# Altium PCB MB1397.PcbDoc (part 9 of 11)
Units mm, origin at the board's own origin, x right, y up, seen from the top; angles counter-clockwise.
Board outline 118.24 x 172.86 mm, 6 copper layers (Top Layer, L2_GND, L3_VCC, L4_SIG, L5_GND, Bottom Layer), stack 1.631 mm thick; 819 components, 632 nets, 2875 pads, 1523 vias.
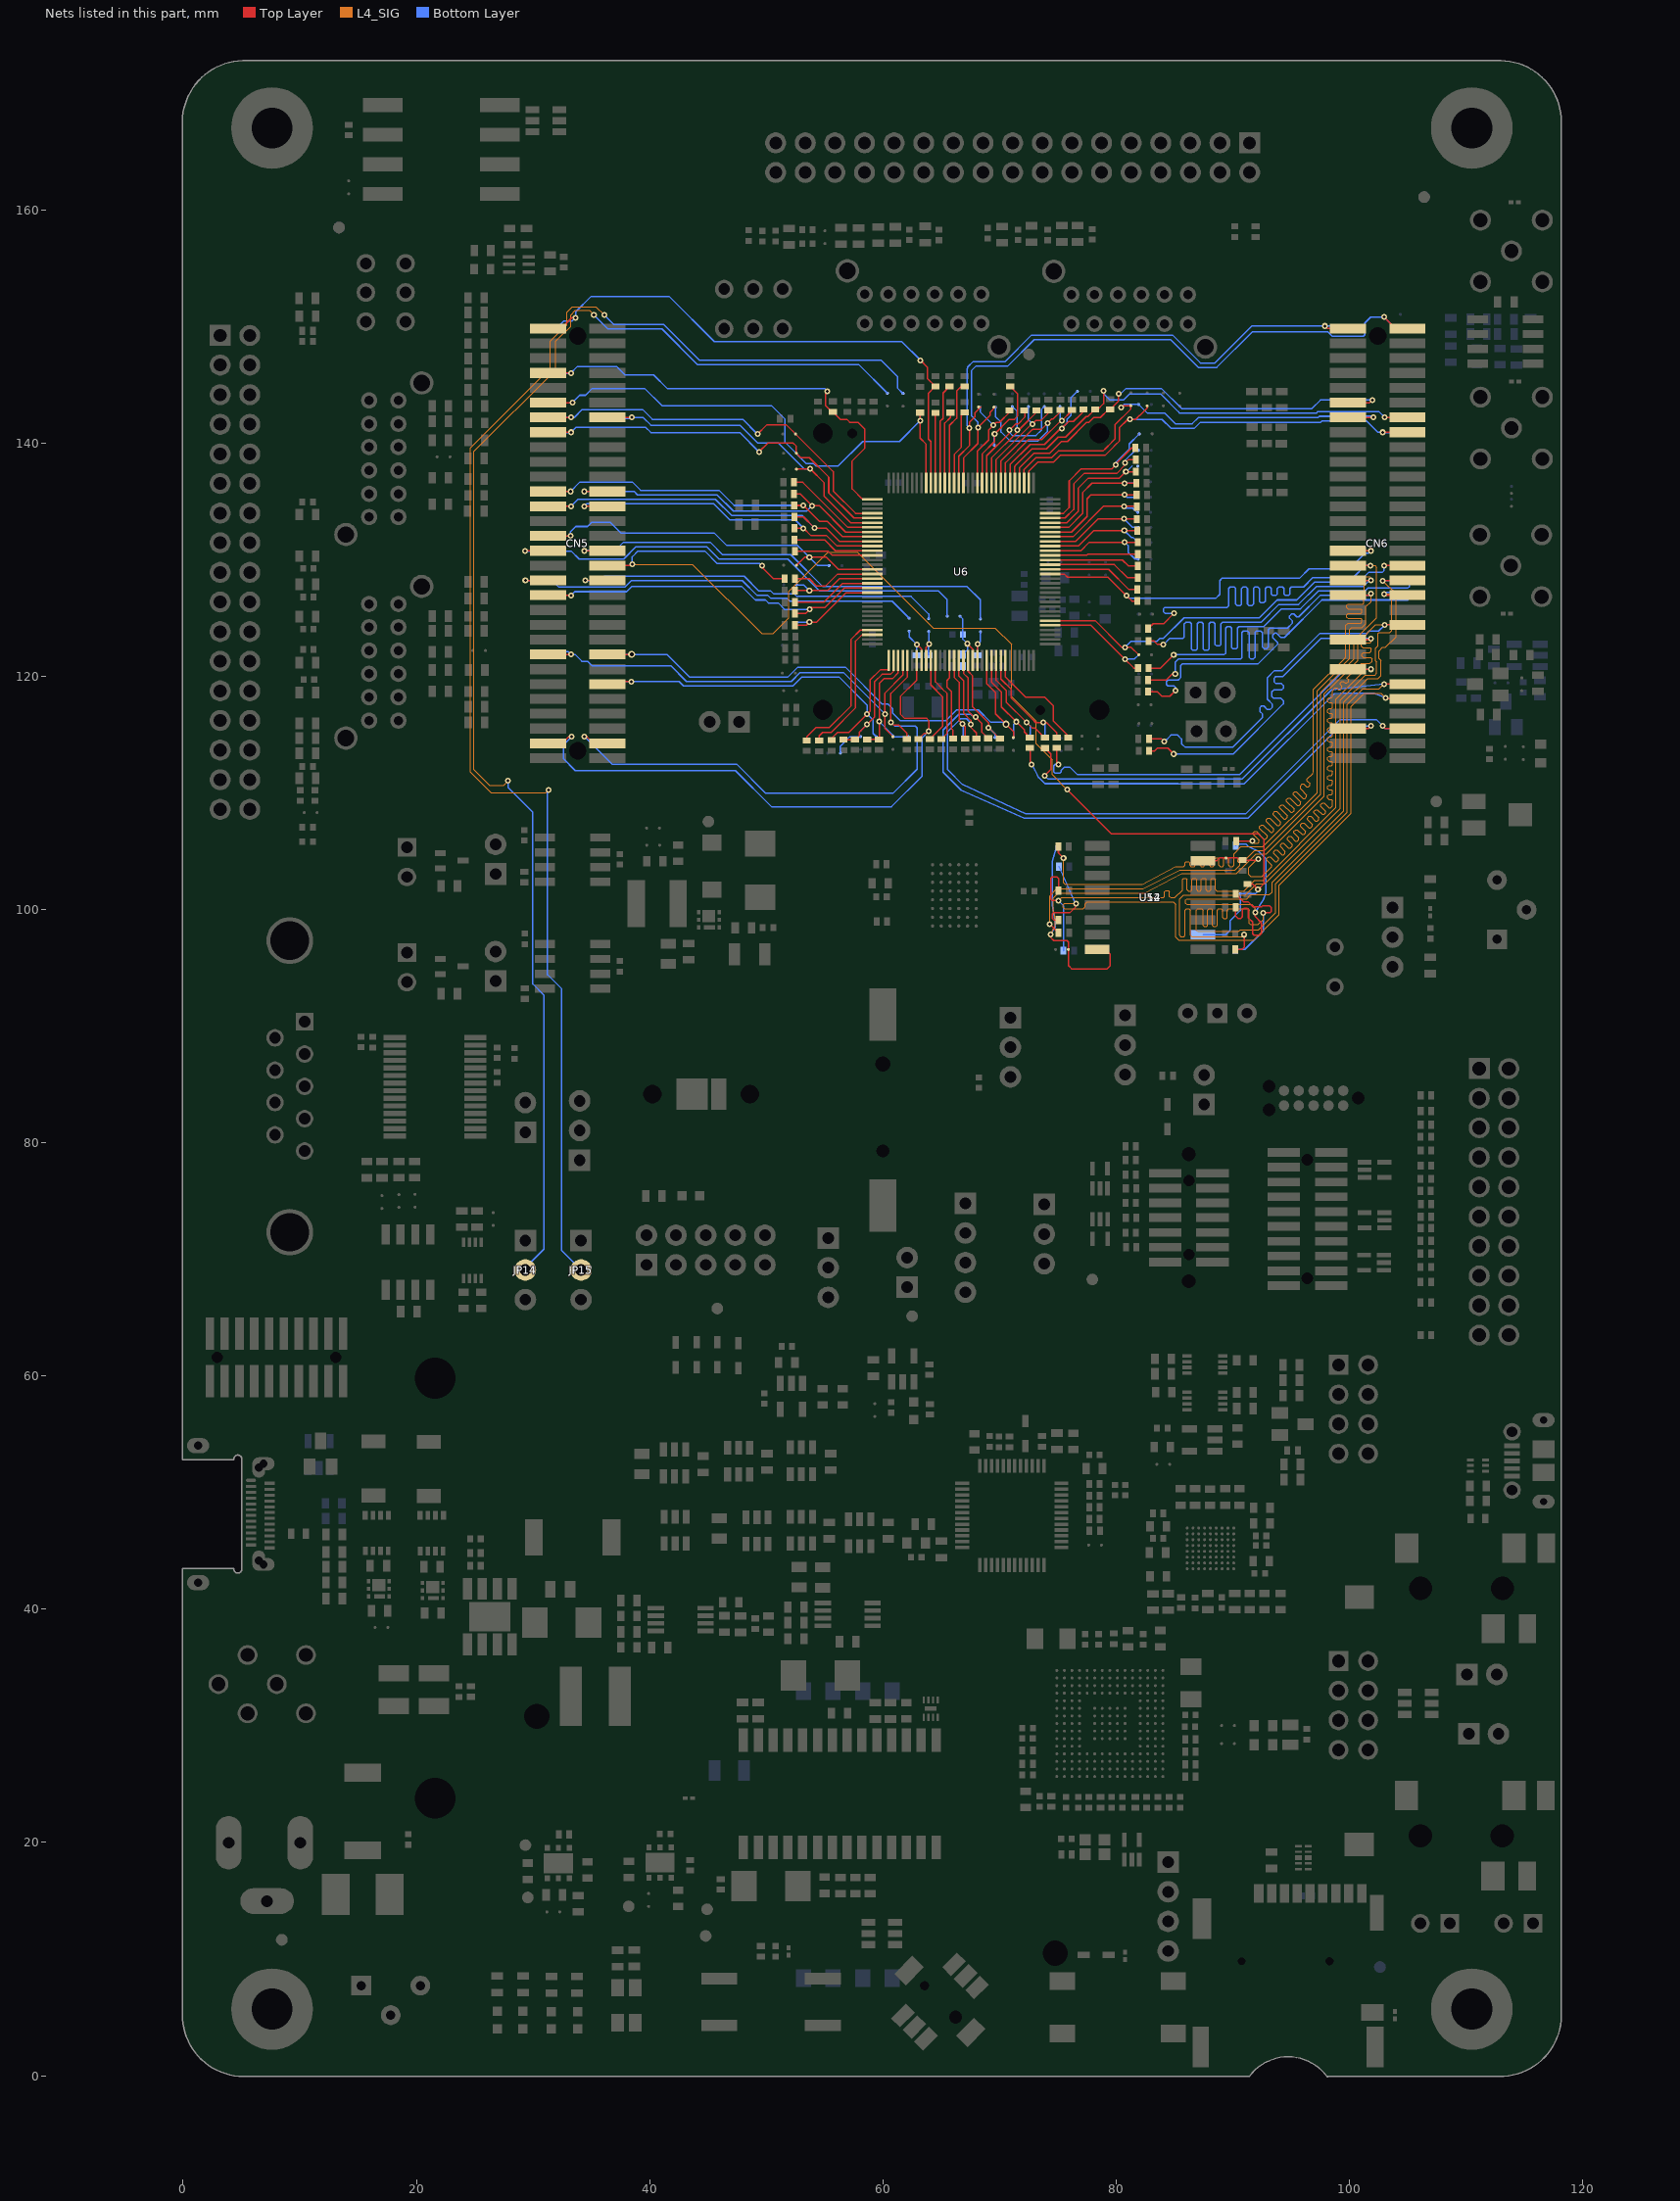
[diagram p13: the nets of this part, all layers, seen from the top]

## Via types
v1: diameter 0.508, hole 0.254, Top Layer to Bottom Layer, tented both sides, 1330 vias
v2: diameter 0.406, hole 0.203, Top Layer to Bottom Layer, tented both sides, 115 vias
v3: diameter 0.508, hole 0.254, Top Layer to Bottom Layer, 33 vias
v4: diameter 0.305, hole 0.152, Top Layer to Bottom Layer, tented both sides, 26 vias
v5: diameter 0.61, hole 0.305, Top Layer to Bottom Layer, tented both sides, 14 vias
v6: diameter 0.61, hole 0.33, Top Layer to Bottom Layer, tented both sides, 2 vias
v7: diameter 0.381, hole 0.203, Top Layer to Bottom Layer, tented both sides, 2 vias
v8: diameter 0.508, hole 0.203, Top Layer to Bottom Layer, tented both sides, 1 vias

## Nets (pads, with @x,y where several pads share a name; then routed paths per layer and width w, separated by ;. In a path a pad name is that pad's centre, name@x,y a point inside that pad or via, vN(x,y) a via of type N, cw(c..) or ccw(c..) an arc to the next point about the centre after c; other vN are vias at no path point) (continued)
PB12: CN6.16 SB7.1 SB65.2 U6.66 | length 40.5
  Top Layer w0.127: U6.66@72.503,136.586 72.502,137.549 ; SB7.1@82.649,143.185 82.649,142.974 82.039,142.364 81.999,142.364 81.658,142.024 v1(81.176,142.024) 80.988,142.024 80.259,141.295 80.259,140.157 79.972,139.87 79.591,139.487 79.046,138.938 75.202,138.938 74.615,138.351 73.266,138.351 72.522,137.607 ; v1(102.842,140.922) 104.965,140.922 CN6.16@104.965,140.921 ; 72.502,137.549 72.522,137.569 72.522,137.607 ; 72.502,137.549 72.502,137.587 72.522,137.607
  Bottom Layer w0.127: v1(81.176,142.024) 83.929,142.024 84.681,141.272 86.713,141.272 87.221,141.78 97.539,141.78 97.666,141.907 101.445,141.907 102.431,140.922 v1(102.842,140.922) 102.873,140.891 SB65.2@104.275,140.891
PB13: CN6.13 SB5.1 SB63.2 U6.67 | length 39.2
  Top Layer w0.127: U6.67@72.103,136.586 72.103,137.729 73.106,138.732 74.455,138.732 74.861,139.138 74.867,139.138 75.045,139.316 78.88,139.316 79.093,139.53 79.591,140.033 79.591,140.048 79.878,140.335 79.878,141.549 81.252,142.923 81.252,143.185 80.548,143.185 v1(80.416,143.053) ; CN6.13@99.865,142.191 99.865,142.192 v1(102.052,142.192)
  Bottom Layer w0.127: v1(80.416,143.053) 80.668,143.304 81.923,143.304 81.923,143.307 82.685,142.542 84.173,142.542 85.06,141.653 86.517,141.653 87.048,142.187 97.31,142.187 97.412,142.288 101.953,142.288 v1(102.052,142.192)
PB14: CN6.11 R35.1 U6.68 | length 37.9
  Top Layer w0.127: U6.68@71.703,136.586 71.702,137.869 72.946,139.113 74.29,139.113 75.306,140.129 75.822,140.129 77.47,141.778 77.663,141.778 78.075,142.189 78.641,142.189 79.327,142.875 R35.1@79.477,142.875 80.211,143.609 v1(80.211,144.219) ; R35.1@79.576,142.875 R35.1@79.599,142.875 ; CN6.11@99.865,143.461 99.865,143.462 101.73,143.462 v1(101.953,143.685)
  Bottom Layer w0.127: v1(80.211,144.219) 80.388,144.219 80.846,144.676 83.873,144.676 85.601,142.949 96.771,142.949 97.508,143.685 101.651,143.685 101.651,143.683 v1(101.953,143.685)
PB15: CN6.14 R36.1 U6.69 | length 40
  Top Layer w0.127: U6.69@71.303,136.586 71.303,137.975 71.321,137.993 71.321,138.029 72.786,139.494 74.013,139.494 75.029,140.51 75.662,140.51 77.417,142.265 77.576,142.265 R36.1@78.194,142.883 78.431,142.883 78.918,143.37 v1(78.918,144.475) ; R36.1@78.248,142.775 78.249,142.775 R36.1@78.268,142.753 ; v1(103.033,142.192) 104.965,142.192 CN6.14@104.965,142.191
  Bottom Layer w0.127: v1(78.918,144.475) 78.918,144.239 79.472,143.685 80.617,143.685 81.125,144.193 83.812,144.193 85.336,142.669 85.339,142.669 85.443,142.568 97.152,142.568 97.254,142.669 102.552,142.669 v1(103.033,142.192)
PC0: CN5.46 SB29.2 SB99.2 U6.22 | length 47.4
  Top Layer w0.127: CN5.46@36.385,121.871 v6(38.453,121.869) ; U6.22@68.903,121.346 68.903,119.362 69.652,118.613 69.652,116.784 v6(70.549,115.888) 71.219,115.217 SB29.2@71.219,114.694
  Bottom Layer w0.127: SB99.2@36.998,121.895 37.023,121.869 v6(38.453,121.869) 41.478,121.869 43.411,119.936 51.864,119.936 52.705,120.777 56.769,120.777 59.944,117.602 60.452,117.602 60.833,117.221 60.833,116.84 61.468,116.202 65.405,116.202 66.322,117.119 68.174,117.119 69.215,116.078 70.358,116.078 v6(70.549,115.888)
PC1: R130.2 SB115.2 U6.23 | length 9.8
  Top Layer w0.127: U6.23@69.303,121.346 69.301,119.504 70.155,118.651 70.155,117.373 v1(71.425,116.103) 72.128,115.4 72.128,115.225 R130.2@72.603,114.75 72.796,114.75 R130.2@72.796,114.739
  Bottom Layer w0.127: SB115.2@71.219,114.694 71.219,115.898 v1(71.425,116.103) v1@71.598,116.103
PC2: R133.2 SB113.2 U6.24 | length 10
  Top Layer w0.127: U6.24@69.703,121.346 69.703,119.644 70.561,118.786 70.561,117.793 v1(72.319,116.035) 72.784,115.57 73.016,115.57 73.848,114.739 R133.2@73.889,114.739 ; R133.2@73.889,114.738 R133.2@73.889,114.738
  Bottom Layer w0.127: v1(72.319,116.035) 72.616,115.738 ; 72.603,115.026 72.616,115.014 ; SB113.2@72.616,114.696 72.616,115.014 ; 72.616,115.776 72.616,115.738 ; 72.616,115.014 72.616,115.738
PC3: R131.2 SB114.2 U6.25 | length 10.5
  Top Layer w0.127: U6.25@70.103,121.346 70.122,121.346 70.122,119.766 71.012,118.876 71.012,118.106 72.778,116.34 ; 72.793,116.325 73.09,116.027 v1(73.736,116.027) 74.038,116.027 74.889,115.179 74.889,114.75 R131.2@74.888,114.75
  Bottom Layer w0.127: v1(73.736,116.027) 73.886,115.877 73.886,115.014 ; SB114.2@73.886,114.694 73.886,115.014 ; 73.889,115.016 73.886,115.014
PC4: R116.2 SB100.2 U6.37 | length 10.4
  Top Layer w0.127: U6.37@74.323,124.363 U6.37@74.323,124.366 77.841,124.366 v1(80.744,121.46) 81.504,120.701 R116.2@81.871,120.701
  Bottom Layer w0.127: v1(80.744,121.46) 81.542,121.46 SB100.2@81.922,121.841
PC5: CN6.34 SB20.2 U6.38 | length 36.2
  Top Layer w0.127: U6.38@74.323,124.766 78.202,124.765 80.49,122.476 v1(80.744,122.476) 81.29,122.476 SB20.2@81.925,121.844 ; v1(102.969,129.489) CN6.34@104.965,129.491
  Bottom Layer w0.127: v1(80.744,122.476) 81.277,123.01 83.513,123.01 83.741,123.238 84.046,123.238 85.824,125.016 92.271,125.016 93.795,126.54 95.479,126.54 97.003,128.064 100.81,128.064 101.674,128.928 102.842,128.928 102.969,129.055 v1(102.969,129.489)
PC6: CN6.2 SB9.2 SB49.2 U6.80 | length 57
  Top Layer w0.127: U6.80@66.903,136.586 66.904,136.586 66.904,138.709 68.146,139.951 v1(68.146,141.323) 69.197,142.377 69.197,142.634 SB9.2@69.642,143.078 ; v1(102.969,150.797) 103.957,149.812 104.965,149.812 CN6.2@104.965,149.811
  Bottom Layer w0.127: v1(68.146,141.323) 68.146,141.78 67.612,142.314 67.612,146.225 67.993,146.606 70.711,146.606 72.972,148.867 84.656,148.867 87.043,146.479 88.618,146.479 91.666,149.527 98.143,149.527 98.524,149.146 101.191,149.146 101.318,149.273 101.318,150.289 101.826,150.797 v1(102.969,150.797) 103.822,149.944 SB49.2@104.366,149.944
PC7: CN6.1 SB6.2 SB50.2 U6.81 | length 50.1
  Top Layer w0.127: U6.81@66.503,136.586 66.502,138.872 67.409,139.779 v1(67.409,141.272) 67.409,141.755 67.892,142.237 67.892,142.591 68.402,143.101 ; v1(97.889,150.035) 98.113,149.812 99.865,149.812 CN6.1@99.865,149.811
  Bottom Layer w0.127: v1(67.409,141.272) 67.231,141.45 67.231,146.383 67.257,146.408 67.257,146.505 67.739,146.987 70.482,146.987 72.743,149.248 84.833,149.248 87.221,146.86 88.461,146.86 91.636,150.035 v1(97.889,150.035) 97.892,150.038 99.195,150.038 SB50.2@99.195,150.035
PC8: CN5.1 R26.2 SB51.2 U6.87 | length 49.2
  Top Layer w0.127: CN5.1@31.285,149.811 32.385,149.809 33.322,150.746 v1(33.652,150.746) ; v1(63.218,147.089) 63.802,146.505 63.802,145.537 R26.2@64.501,144.838 ; U6.87@64.103,136.586 64.102,140.134 63.906,140.332 63.906,144.272 64.47,144.838 R26.2@64.501,144.838 ; R26.2@64.501,144.838 R26.2@64.501,144.838
  Bottom Layer w0.127: SB51.2@31.918,149.809 32.004,149.809 32.662,150.467 33.373,150.467 v1(33.652,150.746) 33.652,151.254 34.973,152.575 41.653,152.575 45.54,148.689 61.615,148.689 v1(63.218,147.089)
PC9: CN5.11 R49.2 U6.88 | length 44.2
  Top Layer w0.127: CN5.11@31.285,143.461 31.285,143.462 v1(33.373,143.462) ; R49.2@63.19,142.601 v1(63.19,141.907) 63.19,140.414 63.703,139.901 U6.88@63.703,136.586
  Bottom Layer w0.127: v1(33.373,143.462) 34.006,144.094 34.493,144.094 35.075,144.676 39.571,144.676 41.044,143.203 50.442,143.203 51.61,142.034 51.61,140.053 53.439,138.224 54.049,138.224 54.251,138.022 56.157,138.022 58.265,140.129 61.412,140.129 v1(63.19,141.907)
PC10: CN5.13 SB12.2 SB64.2 U6.100 | length 35.5
  Top Layer w0.127: CN5.13@31.285,142.191 33.244,142.189 v1(33.246,142.192) ; v1(49.248,140.764) 50.028,141.544 51.734,141.544 ; 52.288,140.988 51.734,141.544 ; U6.100@59.083,133.966 57.661,133.965 55.733,135.893 55.733,137.546 51.735,141.544
  Bottom Layer w0.127: SB64.2@31.971,142.24 32.019,142.192 v1(33.246,142.192) 33.531,142.192 34.214,142.875 39.39,142.875 40.229,142.034 47.976,142.034 v1(49.248,140.764)
PC11: CN5.15 SB13.2 SB68.2 U6.101 | length 34.3
  Top Layer w0.127: CN5.15@31.285,140.921 31.285,140.922 v1(33.246,140.922) ; v1(49.375,139.24) 50.137,140.002 52.296,140.002 52.575,139.725 SB13.2@52.575,139.118 ; SB13.2@52.574,139.119 SB13.2@52.575,139.118 ; U6.101@59.083,133.566 57.506,133.566 55.352,135.72 55.352,137.074 53.693,138.732 52.959,138.732 SB13.2@52.575,139.118
  Bottom Layer w0.127: SB68.2@31.943,140.891 33.218,140.891 v1(33.246,140.922) 33.675,141.351 39.644,141.351 40.104,140.891 47.724,140.891 v1(49.375,139.24)
PC12: CN5.14 SB15.2 SB66.2 U6.102 | length 29.8
  Top Layer w0.127: CN5.14@36.385,142.191 36.386,142.192 v1(38.453,142.192) ; SB15.2@52.527,137.765 SB15.2@52.586,137.765 ; SB15.2@52.586,137.763 SB15.2@52.586,137.765 ; U6.102@59.083,133.166 59.083,133.167 57.229,133.167 54.971,135.423 54.971,136.578 v1(53.772,137.777) 53.757,137.765 SB15.2@52.586,137.765
  Bottom Layer w0.127: SB66.2@37.048,142.113 38.374,142.113 v1(38.453,142.192) 39.439,142.192 40.104,141.526 47.724,141.526 49.235,140.015 51.011,140.015 53.254,137.775 v1(53.772,137.777)
PC13: CN5.57 R141.2 U6.7 | length 51.9
  Top Layer w0.127: CN5.57@31.285,114.251 32.487,114.249 33.043,114.805 v1(33.297,114.805) ; U6.7@62.903,121.346 62.903,119.672 61.493,118.262 61.493,116.759 61.872,116.38 63.751,116.38 63.929,116.202 v1(63.929,115.288) 63.757,115.115 63.543,115.115 63.045,114.615 R141.2@63.043,114.617
  Bottom Layer w0.127: v1(33.297,114.805) 32.611,114.12 32.611,112.928 33.627,111.91 47.343,111.91 50.442,108.811 60.729,108.811 63.345,111.427 63.345,114.704 v1(63.929,115.288)
PC14: R315.2 SB88.1 U6.8 | length 3.9
  Top Layer w0.127: v1(62.903,122.73) 63.302,122.331 U6.8@63.303,121.346
  Bottom Layer w0.127: SB88.1@62.255,123.868 62.255,123.378 v1(62.903,122.73) R315.2@62.903,121.796
PC14_E: CN5.35 SB88.2 | length 36.7
  Top Layer w0.127: v1(29.337,128.219) CN5.35@31.285,128.221
  Bottom Layer w0.127: v1(29.337,128.219) 29.365,128.191 31.648,128.191 32.205,127.635 37.864,127.635 38.423,128.191 47.948,128.191 49.218,126.921 50.137,126.921 50.391,126.667 51.788,126.667 52.017,126.439 60.785,126.439 SB88.2@62.255,124.968
PC15: R314.2 SB87.2 U6.9 | length 3.6
  Top Layer w0.127: U6.9@63.703,121.346 63.703,122.497 v1(63.957,122.751)
  Bottom Layer w0.127: R314.2@63.906,121.796 63.906,122.7 v1(63.957,122.751) 63.929,122.779 SB87.2@63.929,123.837
PC15_E: CN5.36 SB87.1 | length 33.3
  Top Layer w0.102: v1(34.468,128.219) v1(34.468,128.219) CN5.36@36.385,128.221
  Bottom Layer w0.127: v1(34.468,128.219) 35.773,128.219 36.126,128.572 48.105,128.572 49.375,127.302 50.391,127.302 50.645,127.048 52.423,127.048 52.626,126.845 62.408,126.845 63.929,125.324 SB87.1@63.929,124.937
PD0: R83.1 U6.108 | length 7
  Top Layer w0.127: R83.1@52.422,131.695 54.988,131.694 55.918,130.767 59.083,130.767 U6.108@59.083,130.766
PD1: R85.1 U6.109 | length 6.2
  Top Layer w0.127: R85.1@52.444,130.708 55.321,130.708 55.664,130.366 U6.109@58.519,130.366
PD2: CN5.29 SB17.2 SB123.1 U6.112 | length 33
  Top Layer w0.127: CN5.29@31.285,132.031 v1(33.218,132.029) ; SB17.2@52.593,129.515 53.279,130.2 v1(53.693,130.2) 55.169,130.2 56.203,129.164 U6.112@58.519,129.164
  Bottom Layer w0.127: v1(33.218,132.029) 33.218,132.405 33.652,132.839 34.668,132.839 35.024,133.195 36.624,133.195 37.564,132.255 45.565,132.255 46.581,131.239 52.652,131.239 v1(53.693,130.2) 54.406,129.487 SB123.1@55.38,129.487
PD3: R90.1 U6.113 | length 7.3
  Top Layer w0.127: R90.1@52.469,128.366 53.688,128.364 54.331,127.721 55.054,127.721 56.098,128.765 U6.113@59.083,128.766
PD4: R94.1 SB89.2 U6.114 | length 8.3
  Top Layer w0.127: R94.1@52.472,127.341 v1(53.693,127.34) 55.25,127.34 56.276,128.367 59.083,128.367 U6.114@59.083,128.366
  Bottom Layer w0.127: SB89.2@52.597,127.838 53.195,127.838 v1(53.693,127.34)
PD5: R97.1 U6.115 | length 7.3
  Top Layer w0.127: R97.1@52.469,126.365 54.955,126.365 56.556,127.965 U6.115@59.083,127.966
PD6: CN5.37 R98.1 U6.116 | length 31.1
  Top Layer w0.127: CN5.37@31.285,126.951 33.218,126.949 v1(33.246,126.921) ; R98.1@52.469,125.375 53.365,125.374 v1(53.721,125.73) 53.896,125.905 55.037,125.905 56.698,127.566 59.083,127.566 U6.116@59.083,127.566
  Bottom Layer w0.127: v1(33.246,126.921) 33.579,127.254 38.024,127.254 38.453,127.683 47.917,127.683 49.06,126.54 49.929,126.54 50.183,126.286 51.026,126.286 51.582,125.73 v1(53.721,125.73)
PD7: R101.1 SB92.2 U6.117 | length 8.9
  Top Layer w0.127: R101.1@52.469,124.384 53.442,124.384 v1(53.693,124.635) 54.308,124.635 56.838,127.165 U6.117@59.083,127.166
  Bottom Layer w0.127: SB92.2@52.594,124.612 52.619,124.635 v1(53.693,124.635)
PD8: R34.1 SB55.2 U6.70 | length 13.6
  Top Layer w0.127: U6.70@70.903,136.586 70.902,138.151 72.629,139.878 73.856,139.878 75.23,141.252 v1(75.329,141.252) 75.918,141.841 76.332,141.841 76.957,142.464 77.239,142.745 R34.1@77.267,142.745
  Bottom Layer w0.127: v1(75.329,141.252) 75.738,141.661 75.738,141.669 75.796,141.727 75.796,142.055 76.124,142.382 76.124,143.878 76.67,144.424 SB55.2@76.67,144.424
PD9: R37.1 SB56.2 U6.71 | length 11.6
  Top Layer w0.127: U6.71@70.503,136.586 70.503,138.3 72.49,140.288 73.631,140.288 75.255,141.912 v1(75.352,141.912) 76.164,142.725 R37.1@76.251,142.725
  Bottom Layer w0.127: v1(75.352,141.912) v1@75.184,142.08 ; v1@75.184,142.08 75.184,143.121 SB56.2@75.183,143.123 75.181,142.083 v1@75.184,142.08
PD10: R38.1 SB60.2 U6.72 | length 16.5
  Top Layer w0.127: U6.72@70.103,136.586 70.104,136.586 70.104,138.43 70.122,138.448 70.122,138.46 72.809,141.148 72.822,141.148 72.837,141.163 73.576,141.163 v1(74.122,141.712) 74.483,142.072 74.612,142.072 R38.1@75.26,142.718
  Bottom Layer w0.127: SB60.2@69.647,143.064 69.647,142.257 70.126,141.779 70.126,140.941 70.884,140.183 73.304,140.183 74.122,141 v1(74.122,141.712)
PD11: R39.1 SB58.2 U6.73 | length 9.9
  Top Layer w0.127: U6.73@69.703,136.586 69.703,138.582 72.662,141.544 72.664,141.544 72.753,141.633 v1(72.822,141.633) 73.139,141.95 73.581,141.95 74.247,142.613 R39.1@74.247,142.707
  Bottom Layer w0.127: SB58.2@72.479,143.116 72.479,141.976 v1(72.822,141.633)
PD12: R42.1 SB59.2 U6.74 | length 10
  Top Layer w0.127: U6.74@69.303,136.586 69.301,138.722 71.511,140.932 v1(71.511,141.107) 71.625,141.221 71.745,141.221 73.203,142.677 R42.1@73.203,142.679
  Bottom Layer w0.127: SB59.2@71.096,143.116 71.095,143.116 71.511,142.7 v1(71.511,141.107)
PD13: R41.1 SB57.2 U6.75 | length 12.9
  Top Layer w0.127: U6.75@68.903,136.586 68.903,138.9 70.838,140.838 v1(70.838,141.094) 71.371,141.628 71.575,141.628 72.154,142.207 R41.1@72.154,142.677
  Bottom Layer w0.127: v1(70.838,141.094) 70.838,140.896 71.095,140.64 73.127,140.64 73.581,141.094 73.581,142.866 SB57.2@73.831,143.116
PD14: R29.1 SB70.2 U6.76 | length 11
  Top Layer w0.127: U6.76@68.503,136.586 68.504,136.586 68.504,139.065 69.568,140.129 v1(69.568,140.764) 70.836,142.032 71.267,142.032 71.524,142.291 71.524,144.242 R29.1@70.927,144.836
  Bottom Layer w0.127: SB70.2@69.532,139.748 69.532,140.729 v1(69.568,140.764)
PD15: R40.1 SB61.2 U6.77 | length 9.4
  Top Layer w0.127: U6.77@68.103,136.586 68.102,139.299 69.06,140.259 69.06,141.112 v1(69.469,141.521) 69.705,141.755 69.98,141.755 70.9,142.678 70.902,142.679 R40.1@70.902,142.677
  Bottom Layer w0.127: SB61.2@68.329,143.076 68.331,143.076 68.331,142.662 v1(69.469,141.521)
PD_DBCC1: JP15.2 SB54.1 | length 125.5
  L4_SIG w0.102: v1(31.341,110.259) 31.112,110.03 26.388,110.03 24.635,111.783 24.635,139.57 31.493,146.428 31.493,148.717 32.916,150.139 32.916,151.229 33.373,151.686 35.4,151.686 v1(36.101,150.985)
  Bottom Layer w0.127: v1(31.341,110.259) 31.239,110.157 31.239,94.409 32.459,93.19 32.459,70.744 JP15.2@34.117,69.088 ; v1(36.101,150.985) 36.924,150.162 41.201,150.162 44.282,147.081 59.873,147.081 61.237,145.717 61.237,144.734 SB54.1@61.721,144.251
PD_DBCC2: JP14.2 SB53.1 | length 120
  L4_SIG w0.102: v1(27.849,111.046) 27.468,110.665 26.261,110.665 24.94,111.986 24.94,139.266 31.941,146.266 31.941,148.735 33.221,150.012 33.221,150.975 33.627,151.381 34.821,151.381 v1(35.215,150.988)
  Bottom Layer w0.127: v1(27.849,111.046) 27.849,110.475 29.982,108.341 29.982,93.609 30.935,92.657 30.935,70.884 JP14.2@29.337,69.286 ; v1(35.215,150.988) 36.421,149.781 41.044,149.781 44.125,146.7 57.953,146.7 SB53.1@60.376,144.28 SB53.1@60.376,144.277
PE0: R148.2 U6.125 | length 13.1
  Top Layer w0.127: R148.2@53.467,114.488 53.467,114.811 54.259,115.603 55.402,115.603 57.277,117.478 57.277,123.175 58.067,123.965 U6.125@59.083,123.966
PE1: R149.2 U6.126 | length 11.5
  Top Layer w0.127: R149.2@54.534,114.471 54.534,114.889 54.834,115.189 55.55,115.189 57.658,117.297 57.658,123.015 58.209,123.566 U6.126@58.644,123.566
PE2: CN5.50 R147.2 SB103.2 SB111.2 U6.1 | length 38.3
  Top Layer w0.127: CN5.50@36.385,119.331 37.541,119.329 37.755,119.543 v1(38.415,119.543) ; R147.2@55.601,114.521 55.601,114.691 56.096,115.189 57.074,115.189 v1(58.646,116.761) 58.903,117.018 58.903,119.685 59.764,120.546 60.376,120.546 60.503,120.673 U6.1@60.503,121.346
  Bottom Layer w0.127: SB103.2@36.896,119.304 37.135,119.543 v1(38.415,119.543) 42.53,119.543 42.898,119.174 52.294,119.174 52.662,119.543 52.664,119.543 53.058,119.936 56.233,119.936 58.646,117.523 v1(58.646,116.761) 59.154,116.253 59.154,115.098 59.446,114.805 SB111.2@59.446,114.803
PE3: R145.2 R146.2 SB110.2 SB118.2 U6.2 | length 13
  Top Layer w0.127: R146.2@56.617,114.555 57.589,114.554 57.988,114.953 57.988,115.219 v1(58.644,115.875) 59.284,116.515 59.284,119.525 59.921,120.165 60.65,120.165 60.902,120.416 U6.2@60.903,121.346
  Bottom Layer w0.127: SB118.2@56.353,113.411 56.352,114.01 57.158,114.816 58.09,114.816 SB110.2@58.09,114.813 ; 58.09,115.321 v1(58.644,115.875)
PE4: R143.2 R144.2 SB107.2 SB109.2 U6.3 | length 11.9
  Top Layer w0.127: R143.2@58.649,114.588 58.656,114.579 R144.2@59.665,114.581 59.685,114.6 v1(59.685,116.129) 59.685,119.388 60.081,119.784 60.81,119.784 61.303,120.277 U6.3@61.303,121.346
  Bottom Layer w0.127: v1(59.685,116.129) 60.858,114.955 ; SB107.2@60.858,114.824 62.202,114.823 SB109.2@62.202,114.821
PE5: CN5.45 SB28.2 SB97.2 U6.4 | length 40.5
  Top Layer w0.127: CN5.45@31.285,121.871 v1(33.246,121.869) ; SB28.2@60.858,114.824 60.17,115.512 v1(60.17,116.761) 60.17,118.557 61.702,120.089 U6.4@61.703,121.346
  Bottom Layer w0.127: SB97.2@31.941,122.095 33.023,122.095 v1(33.246,121.869) 33.599,121.869 34.183,121.285 34.671,121.285 35.052,120.904 41.808,120.904 43.157,119.555 52.136,119.555 52.898,120.317 56.614,120.317 v1(60.17,116.761)
PE6: CN5.58 R142.2 U6.5 | length 47.7
  Top Layer w0.127: v1(34.414,114.831) 34.618,114.831 35.199,114.249 CN5.58@36.385,114.251 ; R142.2@62.052,114.605 62.052,115.108 61.338,115.821 60.907,115.821 v1(60.703,116.025) 60.678,116.05 60.678,118.524 62.103,119.949 U6.5@62.103,121.346
  Bottom Layer w0.127: v1(34.414,114.831) 36.777,112.469 47.445,112.469 49.959,109.954 60.856,109.954 62.939,112.037 62.939,115.567 62.761,115.745 60.983,115.745 v1(60.703,116.025)
PE7: R84.2 SB83.2 U6.53 | length 9.9
  Top Layer w0.127: U6.53@74.323,130.766 74.323,130.767 76.967,130.767 77.694,131.491 v1@80.721,131.491 ; v1(80.726,131.496) v1@80.721,131.491 ; R84.2@81.837,131.489 81.785,131.491 v1@80.721,131.491
  Bottom Layer w0.127: v1(80.726,131.496) 81.018,131.204 81.018,130.64 81.613,130.045 SB83.2@81.879,130.046
PE8: R82.2 SB79.2 U6.54 | length 9.6
  Top Layer w0.127: U6.54@74.323,131.166 74.325,131.168 74.341,131.186 76.766,131.186 78.064,132.481 v1@80.696,132.481 ; v1(80.696,132.486) v1@80.696,132.481 ; R82.2@81.8,132.48 81.75,132.481 v1@80.696,132.481
  Bottom Layer w0.127: v1(80.696,132.486) 81.275,131.905 81.432,131.905 SB79.2@81.867,131.47
PE9: R79.2 SB78.2 U6.55 | length 9.7
  Top Layer w0.127: U6.55@74.323,131.566 74.323,131.567 76.528,131.567 78.458,133.497 v1(80.67,133.497) 81.702,133.497 R79.2@81.761,133.473
  Bottom Layer w0.127: v1(80.67,133.497) 81.402,132.766 SB78.2@81.867,132.766
PE10: R75.2 SB77.2 U6.56 | length 10
  Top Layer w0.127: U6.56@74.323,131.966 76.297,131.966 78.918,134.587 v1@80.67,134.587 ; v1(80.67,134.569) v1@80.67,134.587 ; R75.2@81.758,134.536 R75.2@81.758,134.587 ; R75.2@81.77,134.587 R75.2@81.758,134.587 ; v1@80.67,134.587 R75.2@81.758,134.587
  Bottom Layer w0.127: v1(80.67,134.569) 80.823,134.417 81.41,134.417 SB77.2@81.852,133.975
PE11: R71.2 SB76.2 U6.57 | length 10.8
  Top Layer w0.127: U6.57@74.323,132.366 76.154,132.364 77.495,133.706 77.495,135.207 77.848,135.56 v1(80.721,135.56) R71.2@81.744,135.56
  Bottom Layer w0.127: v1(80.721,135.56) 80.924,135.357 SB76.2@81.85,135.357
PE12: R69.2 SB74.2 U6.58 | length 11.2
  Top Layer w0.127: U6.58@74.323,132.766 75.928,132.766 77.114,133.952 77.114,135.738 77.927,136.55 v1(80.721,136.55) R69.2@81.719,136.55
  Bottom Layer w0.127: v1(80.721,136.55) 81.717,136.55 SB74.2@81.845,136.679
PE13: R63.2 SB73.2 U6.59 | length 11.1
  Top Layer w0.127: U6.59@74.323,133.166 74.323,133.167 75.789,133.167 76.733,134.112 76.733,136.119 77.572,136.957 80.239,136.957 v1(80.823,137.541) R63.2@81.699,137.541
  Bottom Layer w0.127: v1(80.823,137.541) 80.874,137.541 81.349,138.016
PE14: R62.2 SB72.2 U6.60 | length 12.5
  Top Layer w0.127: U6.60@74.323,133.566 75.611,133.566 76.352,134.308 76.352,136.497 77.241,137.386 80.033,137.386 80.767,138.12 v1(80.767,138.3) 81.049,138.582 R62.2@81.668,138.582
  Bottom Layer w0.127: v1(80.767,138.3) 80.767,138.501 81.636,139.37 SB72.2@81.899,139.37
PE15: R60.2 SB69.2 U6.61 | length 14.7
  Top Layer w0.127: U6.61@74.323,133.966 75.468,133.965 75.971,134.468 75.971,136.756 76.987,137.771 79.628,137.771 v1(79.969,138.113) 80.033,138.176 80.033,138.275 81.331,139.573 R60.2@81.649,139.573
  Bottom Layer w0.127: v1(79.969,138.113) 80.033,138.176 80.033,138.402 81.11,139.479 81.11,139.914 ; 81.183,139.987 81.11,139.914 ; SB69.2@81.91,140.787 SB69.2@81.976,140.787 ; SB69.2@81.978,140.788 81.11,139.92 81.11,139.914
PF0: C172.1 R312.2 R317.2 SB82.1 U6.19 | length 6.3
  Top Layer w0.127: v1(67.246,122.784) 67.704,122.329 67.704,121.346 U6.19@67.703,121.346
  Bottom Layer w0.127: SB82.1@66.607,125.146 66.853,124.9 C172.1@66.853,123.571 66.853,123.177 v1(67.246,122.784) 67.246,122.26 66.853,121.867 R317.2@66.853,120.866
PF0_E: CN5.31 SB82.2 | length 42.2
  Top Layer w0.127: v1(29.309,130.734) 29.334,130.759 CN5.31@31.285,130.761
  Bottom Layer w0.127: v1(29.309,130.734) 30.742,130.734 30.742,130.731 31.841,130.731 31.841,130.734 31.976,130.734 31.976,130.731 33.274,130.731 33.957,130.048 37.77,130.048 38.834,131.112 44.882,131.112 45.946,130.048 51.836,130.048 54.582,127.302 64.773,127.302 65.507,126.568 SB82.2@65.507,125.146
PF1: R313.2 SB81.2 U6.20 | length 3.5
  Top Layer w0.127: U6.20@68.103,121.346 v1(68.102,122.743)
  Bottom Layer w0.127: R313.2@68.103,121.796 v1(68.102,122.743) 68.351,122.992 SB81.2@68.351,123.811
PF1_E: CN5.32 SB81.1 | length 40
  Top Layer w0.127: v1(34.389,130.759) CN5.32@36.385,130.761
  Bottom Layer w0.127: v1(34.389,130.759) 34.44,130.81 37.071,130.81 37.755,131.493 45.184,131.493 46.248,130.429 52.09,130.429 54.836,127.683 67.223,127.683 68.351,126.555 SB81.1@68.351,124.911
PF2: R132.1 U6.26 | length 9.8
  Top Layer w0.127: U6.26@70.503,121.346 70.503,119.926 72.212,118.217 73.856,118.217 74.601,117.471 74.601,116.178 75.888,114.892 R132.1@75.888,114.75
PF3: R139.1 U6.10 | length 7.6
  Top Layer w0.127: R139.1@64.028,114.623 65.123,115.717 65.123,118.234 64.102,119.256 U6.10@64.103,121.346
PF4: R140.1 U6.11 | length 7.3
  Top Layer w0.127: U6.11@64.503,121.346 64.503,119.517 65.105,118.915 65.105,118.908 65.504,118.509 65.504,115.11 R140.1@65.016,114.623
PF5: R137.1 U6.14 | length 7
  Top Layer w0.127: U6.14@65.703,121.346 65.702,121.117 65.717,121.102 65.717,119.868 65.702,119.852 65.486,119.634 65.486,119.065 65.885,118.666 65.885,115.491 66.015,115.364 R137.1@66.015,114.648
PF6: CN5.7 R43.1 SB52.2 U6.97 | length 39.5
  Top Layer w0.127: CN5.7@31.285,146.001 31.285,146.002 v1(33.246,146.002) ; v1(55.235,144.447) 55.067,144.28 55.067,143.231 55.697,142.601 55.776,142.601 56.342,142.034 56.896,142.034 57.147,141.783 57.848,141.783 58.42,141.211 58.42,139.522 57.356,138.458 57.356,136.065 58.255,135.166 59.083,135.166 U6.97@59.083,135.166
  Bottom Layer w0.127: SB52.2@31.941,145.971 33.216,145.971 v1(33.246,146.002) 33.777,146.533 37.186,146.533 37.874,145.844 40.333,145.844 41.526,144.65 55.032,144.65 v1(55.235,144.447)
PF7: R138.1 SB108.2 U6.15 | length 8.2
  Top Layer w0.127: R138.1@67.039,114.648 67.038,115.689 v1(66.827,115.9) 66.548,116.18 66.548,119.456 66.472,119.532 66.472,119.537 66.103,119.906 U6.15@66.103,121.343 ; U6.15@66.103,121.343 U6.15@66.103,121.346 66.103,121.346 U6.15@66.103,121.343
  Bottom Layer w0.127: v1(66.827,115.9) 66.878,115.849 SB108.2@66.878,114.815
PF8: CN6.56 R135.1 SB106.2 U6.16 | length 59
  Top Layer w0.127: U6.16@66.503,121.346 66.502,120.043 66.929,119.616 66.929,116.83 67.539,116.215 v1(67.539,115.872) 67.539,115.616 68.016,115.138 R135.1@68.016,114.665 ; v1(102.842,115.745) 103.068,115.519 CN6.56@104.965,115.521
  Bottom Layer w0.127: v1(67.539,115.872) 67.539,115.976 67.165,116.35 66.667,116.35 66.662,116.345 66.642,116.345 65.529,115.232 65.529,112.006 66.822,110.714 72.235,108.227 91.13,108.227 99.157,116.253 102.334,116.253 v1(102.842,115.745) 103.066,115.519 SB106.2@104.365,115.521
PF9: CN6.55 R134.1 U6.17 | length 57.9
  Top Layer w0.127: U6.17@66.903,121.346 66.904,121.346 66.904,120.251 67.31,119.845 67.31,116.99 67.803,116.495 v1(67.937,116.495) 68.489,115.943 68.489,115.197 R134.1@69.012,114.674 ; CN6.55@99.865,115.521 101.6,115.519 v1(101.826,115.745)
  Bottom Layer w0.127: v1(67.937,116.495) 67.8,116.495 67.559,116.738 66.495,116.738 65.275,115.519 65.275,115.517 65.148,115.39 65.148,111.783 66.711,110.221 72.108,107.82 91.283,107.82 99.207,115.745 v1(101.826,115.745)
PF10: R136.1 SB112.2 U6.18 | length 8.9
  Top Layer w0.127: U6.18@67.303,121.346 67.302,120.426 67.691,120.038 67.691,117.371 69.06,116.002 v1(69.06,115.593) 69.091,115.593 69.218,115.466 69.218,115.463 70.015,114.666 70.028,114.666 R136.1@70.029,114.665
  Bottom Layer w0.127: v1(69.06,115.593) 69.604,115.049 SB112.2@69.604,114.757
PF11: CN6.31 R96.1 U6.48 | length 35
  Top Layer w0.127: U6.48@74.323,128.766 75.557,128.765 75.823,128.499 79.294,128.499 v1(80.871,126.921) ; CN6.31@99.865,130.761 v1(101.826,130.759) ; v1(80.871,126.921) 81.343,126.451 81.811,126.451 R96.1@81.812,126.451 81.341,126.449 v1(80.871,126.921)
  Bottom Layer w0.127: v1(80.871,126.921) 81.123,126.667 88.522,126.667 88.885,127.03 88.885,128.204 89.101,128.42 95.743,128.42 96.53,129.207 99.987,129.207 101.318,130.541 101.608,130.541 v1(101.826,130.759)
PF12: R93.1 U6.49 | length 8.2
  Top Layer w0.127: U6.49@74.323,129.166 74.323,129.167 79.345,129.167 81.054,127.455 R93.1@81.812,127.455
PF13: R89.1 U6.50 | length 8
  Top Layer w0.127: U6.50@74.323,129.566 79.84,129.565 80.962,128.443 81.791,128.443 R89.1@81.842,128.441
PF14: R88.1 U6.51 | length 7.7
  Top Layer w0.127: U6.51@74.323,129.966 74.323,129.967 80.536,129.967 81.041,129.459 81.785,129.459 R88.1@81.837,129.457
PF15: R87.1 U6.52 | length 7.6
  Top Layer w0.127: U6.52@74.323,130.366 77.457,130.366 77.561,130.47 81.803,130.47 R87.1@81.855,130.468
PG0: R48.1 U6.82 | length 6.4
  Top Layer w0.127: R48.1@67.003,142.624 66.708,142.329 66.708,142.11 66.698,142.1 66.698,139.609 66.103,139.014 U6.82@66.103,136.586 ; U6.82@66.103,136.586 U6.82@66.103,136.586 66.103,136.583 U6.82@66.103,136.586
PG1: R28.1 U6.83 | length 9
  Top Layer w0.127: U6.83@65.703,136.586 65.702,141.506 66.317,142.118 66.317,142.258 66.327,142.268 66.327,143.835 66.317,143.845 66.317,144.447 66.705,144.838 67.003,144.838 R28.1@67.003,144.838
PG2: R50.1 U6.84 | length 6.4
  Top Layer w0.127: U6.84@65.301,136.586 U6.84@65.303,136.586 65.303,141.707 65.786,142.189 R50.1@65.786,142.603 R50.1@65.786,142.827
PG3: R27.1 U6.85 | length 8.6
  Top Layer w0.127: U6.85@64.903,136.586 64.902,141.859 65.151,142.108 65.151,144.287 65.702,144.838 R27.1@65.703,144.838
PG4: R53.1 U6.86 | length 6
  Top Layer w0.127: R53.1@64.501,142.574 64.501,142.575 64.503,142.575 U6.86@64.503,136.586
PG5: R68.1 U6.103 | length 8.3
  Top Layer w0.127: R68.1@52.368,136.627 53.132,136.627 56.993,132.766 U6.103@59.083,132.766
PG6: CN5.24 R70.1 U6.104 | length 30.5
  Top Layer w0.127: v1(34.389,135.842) 36.386,135.842 CN5.24@36.385,135.841 ; R70.1@52.369,135.636 R70.1@52.369,135.636 52.906,135.636 v1(53.922,134.617) 54.552,134.617 56.805,132.364 U6.104@59.083,132.366
  Bottom Layer w0.127: v1(34.389,135.842) 38.677,135.842 38.961,135.557 45.789,135.557 47.186,134.16 53.464,134.16 v1(53.922,134.617)
PG7: CN5.23 R74.1 U6.105 | length 30.9
  Top Layer w0.127: CN5.23@31.285,135.841 31.285,135.842 v1(33.216,135.842) ; R74.1@52.394,134.645 v1(53.185,134.645) 54.534,133.297 55.212,133.297 56.543,131.966 U6.105@59.083,131.966
  Bottom Layer w0.127: v1(33.216,135.842) 34.026,136.652 38.501,136.652 39.215,135.938 45.946,135.938 47.239,134.645 v1(53.185,134.645)
PG8: CN5.25 R78.1 U6.106 | length 31.7
  Top Layer w0.127: CN5.25@31.285,134.571 v1(33.246,134.569) ; R78.1@52.41,133.666 53.185,133.665 v1(54.145,132.707) 55.126,132.707 56.266,131.567 59.083,131.567 U6.106@59.083,131.566
  Bottom Layer w0.127: v1(33.246,134.569) 33.853,135.176 45.631,135.176 47.028,133.779 53.068,133.779 v1(54.145,132.707)
PG9: CN5.26 R81.1 U6.107 | length 29.1
  Top Layer w0.127: v1(34.389,134.569) CN5.26@36.385,134.571 ; R81.1@52.422,132.69 v1(53.185,132.69) 53.8,132.075 55.148,132.075 56.058,131.166 U6.107@59.083,131.166
  Bottom Layer w0.127: v1(34.389,134.569) 34.615,134.795 45.471,134.795 46.868,133.398 52.474,133.398 v1(53.185,132.69)
QSPI_BK1_IO0: CN6.33 R102.2 R173.2 | length 89.3
  Top Layer w0.127: v1(74.295,98.755) 75.062,97.991 R173.2@75.087,97.965 ; R102.2@82.744,124.079 83.172,124.508 84.071,124.508 v1(84.96,125.397) ; CN6.33@99.865,129.491 v1(101.798,129.489)
  L4_SIG w0.102: v1(74.295,98.755) 74.295,101.168 74.902,101.775 82.309,101.775 85.433,103.375 90.167,103.375 90.597,103.805 90.597,103.95 90.449,104.097 90.449,104.242 90.594,104.386 90.736,104.386 90.886,104.237 91.029,104.237 91.869,105.077 92.707,105.077 97.533,109.903 97.533,118.617 98.536,119.619 98.539,119.619 100.399,121.48 100.399,123.081 102.334,125.016 102.334,129.334 102.179,129.489 v1(101.798,129.489)
  Bottom Layer w0.127: v1(84.96,125.397) 84.173,125.397 84.046,125.524 84.046,125.778 84.173,125.905 89.507,125.905 89.647,126.045 89.647,127.531 89.774,127.658 90.114,127.658 90.241,127.531 90.241,126.19 90.368,126.063 90.622,126.063 90.749,126.19 90.749,127.531 90.876,127.658 91.13,127.658 91.257,127.531 91.257,126.19 91.384,126.063 91.638,126.063 91.765,126.19 91.765,127.531 91.892,127.658 92.146,127.658 92.273,127.531 92.273,126.444 92.4,126.317 92.654,126.317 92.781,126.444 92.781,127.531 92.908,127.658 93.175,127.658 93.302,127.531 93.302,127.048 93.429,126.921 93.683,126.921 93.81,127.048 93.81,127.531 93.937,127.658 94.262,127.658 94.389,127.531 94.389,127.048 94.516,126.921 94.77,126.921 94.897,127.048 94.897,127.531 95.024,127.658 96.058,127.658 96.845,128.445 100.302,128.445 101.346,129.489 v1(101.798,129.489)
QSPI_BK1_IO1: CN6.35 R108.2 R159.1 | length 90.2
  Top Layer w0.127: R108.2@82.771,123.018 83.251,123.017 83.538,122.73 v1(84.046,122.73) ; R159.1@90.28,105.861 90.282,105.862 v1(91.666,105.862) ; CN6.35@99.865,128.221 v1(101.826,128.219)
  L4_SIG w0.102: v1(91.666,105.862) 91.841,105.687 92.149,105.687 92.25,105.788 92.25,105.941 91.76,106.431 91.76,106.573 91.869,106.683 92.014,106.683 92.659,106.037 92.804,106.037 92.946,106.18 92.946,106.324 92.301,106.97 92.301,107.114 92.443,107.257 92.588,107.257 93.236,106.611 93.378,106.611 93.523,106.756 93.523,106.898 92.875,107.546 92.875,107.688 93.02,107.833 93.165,107.833 93.81,107.185 93.955,107.185 94.097,107.33 94.097,107.475 93.452,108.12 93.452,108.265 93.594,108.407 93.739,108.407 94.384,107.762 94.529,107.762 94.673,107.904 94.673,108.049 94.026,108.697 94.026,108.839 94.17,108.984 94.313,108.984 94.96,108.336 95.103,108.336 95.247,108.481 95.247,108.623 94.602,109.271 94.602,109.416 94.745,109.558 94.889,109.558 95.534,108.913 95.679,108.913 95.822,109.055 95.822,109.2 95.176,109.845 95.176,109.99 95.303,110.117 95.448,110.117 96.042,109.522 96.185,109.522 96.329,109.667 96.329,109.812 95.799,110.34 95.799,110.612 95.943,110.757 96.086,110.757 96.337,110.505 96.482,110.505 96.624,110.647 96.624,110.792 96.373,111.044 96.373,111.186 96.855,111.669 96.855,111.714 96.924,111.783 96.924,118.869 99.592,121.537 ; 99.048,120.993 99.593,121.537 ; 99.594,121.537 99.593,121.537 ; v1(101.826,128.219) 101.826,128.422 101.724,128.524 101.369,128.524 101.267,128.422 101.267,127.15 101.14,127.023 99.87,127.023 99.769,126.921 99.769,126.693 99.87,126.591 101.14,126.591 101.242,126.489 101.242,126.286 101.14,126.185 99.87,126.185 99.769,126.083 99.769,125.88 99.87,125.778 100.962,125.778 101.064,125.677 101.064,125.473 100.962,125.372 99.87,125.372 99.769,125.27 99.769,125.067 99.87,124.965 100.962,124.965 101.064,124.864 101.064,124.661 100.962,124.559 99.87,124.559 99.695,124.384 99.695,121.64 99.593,121.537
  Bottom Layer w0.127: v1(84.046,122.73) 84.077,122.73 84.585,123.238 85.712,123.238 85.839,123.365 85.839,124.493 85.982,124.635 86.314,124.635 86.441,124.508 86.441,122.349 86.568,122.222 86.822,122.222 86.949,122.349 86.949,124.508 87.076,124.635 87.33,124.635 87.457,124.508 87.457,122.349 87.584,122.222 87.838,122.222 87.965,122.349 87.965,124.508 88.092,124.635 88.346,124.635 88.473,124.508 88.473,122.73 88.6,122.603 88.854,122.603 88.981,122.73 88.981,124.508 89.108,124.635 92.428,124.635 93.952,126.159 95.636,126.159 97.16,127.683 101.161,127.683 101.415,127.937 101.417,127.937 101.699,128.219 v1(101.826,128.219)
QSPI_BK1_IO2: CN6.37 R118.1 R160.2 | length 88.2
  Top Layer w0.127: R160.2@75.047,105.408 75.047,104.856 v1(75.486,104.417) ; R118.1@82.746,119.667 84.285,119.667 84.808,120.19 v1(85.062,120.19) ; CN6.37@99.865,126.951 101.727,126.949 v1(101.851,127.074)
  L4_SIG w0.102: v1(75.486,104.417) 75.486,102.436 75.481,102.431 75.481,102.288 75.613,102.156 82.23,102.156 85.049,103.68 85.796,103.68 85.898,103.782 85.898,104.01 85.999,104.112 86.203,104.112 86.304,104.01 86.304,103.782 86.406,103.68 86.68,103.68 86.782,103.782 86.782,104.341 86.883,104.442 87.086,104.442 87.188,104.341 87.188,103.782 87.29,103.68 87.493,103.68 87.594,103.782 87.594,104.341 87.696,104.442 87.899,104.442 88.001,104.341 88.001,103.782 88.102,103.68 88.306,103.68 88.407,103.782 88.407,104.341 88.509,104.442 88.712,104.442 88.814,104.341 88.814,103.782 88.915,103.68 89.118,103.68 89.22,103.782 89.22,104.341 89.322,104.442 89.525,104.442 89.626,104.341 89.626,103.782 89.728,103.68 89.964,103.68 90.091,103.807 90.091,104.772 90.701,105.382 92.58,105.382 97.229,110.03 97.229,118.743 98.41,119.924 98.412,119.924 100,121.512 100,124.003 100.175,124.178 101.064,124.178 101.394,124.508 101.394,125.956 101.851,126.413 v1(101.851,127.074)
  Bottom Layer w0.127: v1(85.062,120.19) 85.062,121.206 85.316,121.46 90.65,121.46 90.777,121.587 90.777,123.746 90.904,123.873 91.26,123.873 91.387,123.746 91.387,121.618 91.514,121.491 91.768,121.491 91.895,121.618 91.895,123.746 92.022,123.873 92.403,123.873 92.53,123.746 92.53,122.507 92.657,122.38 92.911,122.38 93.038,122.507 93.038,124 93.165,124.127 94.684,124.127 95.113,124.557 95.113,124.737 94.861,124.986 94.861,125.164 95.042,125.344 95.222,125.344 95.471,125.095 95.651,125.095 97.478,126.921 101.699,126.921 v1(101.851,127.074)
QSPI_BK1_IO3: CN6.38 R121.1 R178.1 | length 88.5
  Top Layer w0.127: R121.1@82.734,118.684 83.505,118.684 83.905,118.285 84.597,118.285 v1(85.085,118.773) ; R178.1@90.212,96.569 90.777,96.568 90.98,96.771 v1(90.98,97.838) ; v1(102.969,127.048) 103.068,126.949 CN6.38@104.965,126.951
  L4_SIG w0.102: v1(90.98,97.838) 90.828,97.686 86.484,97.686 86.383,97.787 86.383,99.921 86.256,100.048 86.02,100.048 85.918,99.946 85.918,97.787 85.816,97.686 85.545,97.686 85.443,97.787 85.443,100.912 85.778,101.247 91.062,101.247 92.024,102.207 92.733,102.207 99.21,108.684 99.21,117.958 101.369,120.114 102.179,120.114 102.334,120.269 102.334,121.214 102.232,121.315 102.232,122.4 102.436,122.603 102.436,123.645 102.537,123.746 103.452,123.746 103.604,123.899 103.604,126.896 103.452,127.048 v1(102.969,127.048)
  Bottom Layer w0.127: v1(85.085,118.773) 85.085,119.047 84.958,119.174 84.427,119.174 84.3,119.301 84.3,119.555 84.427,119.682 85.316,119.682 85.507,119.873 85.507,120.889 85.697,121.079 92.174,121.079 93.825,122.73 93.825,122.911 93.419,123.317 93.419,123.53 93.581,123.693 93.762,123.693 94.122,123.332 94.427,123.332 97.635,126.54 105.001,126.54 105.128,126.667 105.128,127.048 105.001,127.175 103.096,127.175 v1(102.969,127.048)
QSPI_BK1_NCS: CN6.43 R150.1 R161.2 SB35.1 U12.7 | length 85.3
  Top Layer w0.127: R150.1@82.718,113.713 R150.1@82.845,113.84 ; R150.1@82.822,113.6 83.298,113.6 83.538,113.84 84.427,113.84 v1(84.935,113.332) ; U12.7@87.454,104.189 88.618,104.188 88.839,104.412 SB35.1@89.418,104.412 89.444,104.437 89.761,104.437 ; 90.079,104.437 89.761,104.437 ; v1(92.174,104.315) 92.093,104.234 90.841,104.234 R161.2@90.839,104.233 90.584,104.231 90.381,104.435 89.761,104.435 89.761,104.437 ; CN6.43@99.865,123.141 101.727,123.139 v1(101.826,123.238)
  L4_SIG w0.102: v1(92.174,104.315) 92.072,104.315 91.361,103.604 91.361,102.994 91.539,102.817 92.479,102.817 93.337,103.675 93.337,103.817 92.921,104.234 92.921,104.376 93.066,104.521 93.21,104.521 93.624,104.107 93.769,104.107 93.911,104.249 93.911,104.394 93.497,104.808 93.497,104.953 93.642,105.098 93.784,105.098 94.201,104.681 94.343,104.681 94.488,104.826 94.488,104.968 94.071,105.385 94.071,105.527 94.216,105.672 94.358,105.672 94.775,105.255 94.917,105.255 95.08,105.418 95.08,105.562 94.666,105.976 94.666,106.121 94.811,106.266 94.953,106.266 95.369,105.849 95.512,105.849 95.656,105.994 95.656,106.136 95.24,106.553 95.24,106.695 95.385,106.84 95.529,106.84 95.943,106.426 96.088,106.426 96.23,106.568 96.23,106.713 95.816,107.127 95.816,107.272 95.959,107.414 96.103,107.414 96.517,107 96.662,107 96.807,107.145 96.807,107.287 96.39,107.704 96.39,107.846 96.535,107.991 96.677,107.991 97.094,107.574 97.236,107.574 97.381,107.719 97.381,107.864 96.967,108.278 96.967,108.422 97.109,108.565 97.254,108.565 97.668,108.151 97.813,108.151 97.955,108.293 97.955,108.438 97.541,108.852 97.541,108.996 97.686,109.141 97.828,109.141 98.245,108.725 98.387,108.725 98.549,108.887 98.549,109.339 98.448,109.441 98.245,109.441 98.143,109.543 98.143,109.746 98.245,109.847 98.448,109.847 98.549,109.949 98.549,110.152 98.448,110.254 98.245,110.254 98.143,110.355 98.143,110.559 98.245,110.66 98.448,110.66 98.549,110.762 98.549,110.99 98.448,111.092 98.245,111.092 98.143,111.194 98.143,111.397 98.245,111.498 98.448,111.498 98.549,111.6 98.549,111.803 98.448,111.905 98.245,111.905 98.143,112.006 98.143,112.21 98.245,112.311 98.448,112.311 98.549,112.413 98.549,112.616 98.448,112.718 98.245,112.718 98.143,112.819 98.143,113.022 98.245,113.124 98.448,113.124 98.549,113.226 98.549,113.429 98.448,113.53 98.245,113.53 98.143,113.632 98.143,113.835 98.245,113.937 98.448,113.937 98.549,114.038 98.549,114.275 98.448,114.376 98.245,114.376 98.143,114.478 98.143,114.681 98.245,114.783 98.448,114.783 98.549,114.884 98.549,115.087 98.448,115.189 98.245,115.189 98.143,115.291 98.143,115.494 98.245,115.595 98.448,115.595 98.549,115.697 98.549,115.9 98.448,116.002 98.245,116.002 98.143,116.103 98.143,116.307 98.245,116.408 98.448,116.408 98.549,116.51 98.549,116.713 98.448,116.815 98.245,116.815 98.143,116.916 98.143,117.119 98.245,117.221 98.448,117.221 98.549,117.323 98.549,117.64 98.448,117.742 98.245,117.742 98.143,117.843 98.143,118.047 98.245,118.148 98.448,118.148 98.549,118.25 98.549,118.768 98.768,118.989 98.913,118.989 99.06,118.839 99.205,118.839 99.347,118.984 99.347,119.126 99.2,119.276 99.2,119.418 99.344,119.563 99.487,119.563 99.637,119.413 99.779,119.413 99.924,119.558 99.924,119.703 99.774,119.85 101.034,121.11 101.755,121.11 101.928,121.282 101.928,121.486 101.826,121.587 101.191,121.587 101.064,121.714 101.064,121.892 101.191,122.019 101.75,122.019 101.877,122.146 101.877,122.349 101.775,122.451 101.14,122.451 101.039,122.552 101.039,122.756 101.14,122.857 101.775,122.857 101.877,122.959 101.877,123.187 v1(101.826,123.238)
  Bottom Layer w0.127: v1(84.935,113.332) 90.037,113.332 94.333,117.629 94.333,117.907 94.13,118.11 93.505,118.11 93.345,118.27 93.345,118.669 93.497,118.821 94.183,118.821 94.333,118.971 94.333,119.202 94.167,119.368 93.684,119.368 93.528,119.525 93.528,119.82 93.672,119.964 94.285,119.964 97.559,123.238 v1(101.826,123.238)
QSPI_BK2_IO0: CN6.52 R130.1 R170.2 R320.2 | length 93.1
  Top Layer w0.127: R130.1@72.603,113.85 72.616,113.835 72.616,112.57 v1(72.743,112.443) ; R170.2@75.047,99.086 74.671,99.085 74.521,99.235 74.521,99.616 74.648,99.743 76.045,99.743 76.553,100.251 v1(76.553,100.505) ; v1(103.096,118.158) 103.195,118.059 CN6.52@104.965,118.061
  L4_SIG w0.102: v1(76.553,100.505) 75.588,100.505 75.461,100.378 75.461,100.175 75.588,100.048 77.163,100.048 77.34,100.226 77.34,100.48 77.493,100.632 84.91,100.632 85.113,100.429 85.113,97.61 85.341,97.381 91.793,97.381 93.977,99.565 93.977,102.078 100.15,108.25 100.15,117.422 101.267,118.539 102.715,118.539 v1(103.096,118.158)
  Bottom Layer w0.127: v1(72.743,112.443) 73.028,111.948 73.363,111.316 73.886,110.792 85.316,110.792 85.34,110.768 90.969,110.768 98.684,118.484 99.2,118.539 102.08,118.539 v1(103.096,118.158) ; R320.2@75.088,103.681 76.5,100.526 v1(76.553,100.505)
QSPI_BK2_IO1: CN6.50 R133.1 R168.1 R321.1 | length 94.7
  Top Layer w0.127: v1(73.861,111.478) 74.394,112.011 74.394,113.33 R133.1@73.889,113.838 ; R168.1@90.235,101.349 90.95,100.632 91.336,100.632 91.74,100.228 92.453,100.228 92.527,100.302 93.165,100.302 93.292,100.175 93.292,99.84 93.165,99.713 v1(92.613,99.713) ; v1(102.969,119.329) CN6.50@104.965,119.331
  L4_SIG w0.102: v1(92.613,99.713) 92.613,99.141 92.174,98.702 91.514,98.702 91.412,98.803 91.412,99.946 91.31,100.048 89.626,100.048 89.525,99.946 89.525,99.311 89.423,99.21 89.22,99.21 89.118,99.311 89.118,99.946 89.017,100.048 88.76,100.048 88.659,99.946 88.659,98.651 88.557,98.549 88.354,98.549 88.252,98.651 88.252,99.946 88.151,100.048 87.947,100.048 87.846,99.946 87.846,98.651 87.744,98.549 87.541,98.549 87.439,98.651 87.439,99.946 87.338,100.048 86.992,100.048 86.878,99.934 86.878,98.219 86.98,98.118 90.498,98.118 90.65,98.27 92.199,98.27 93.673,99.743 93.673,102.205 99.819,108.351 99.819,117.574 101.143,118.897 102.537,118.897 v1(102.969,119.329)
  Bottom Layer w0.127: v1(73.861,111.478) 74.163,111.173 90.781,111.173 98.45,118.843 v1(102.969,119.329) ; R321.1@90.212,96.569 91.031,96.568 92.613,98.151 v1(92.613,99.713)
QSPI_BK2_IO2: CN6.47 R131.1 R167.2 R322.2 | length 93.7
  Top Layer w0.127: R131.1@74.888,113.85 74.887,112.586 v1(75.029,112.443) ; v1(75.052,100.759) 74.521,100.759 74.394,100.886 74.394,102.664 74.521,102.791 74.925,102.791 75.052,102.664 R167.2@75.052,101.626 ; CN6.47@99.865,120.601 v1(101.826,120.599)
  L4_SIG w0.102: v1(75.052,100.759) 75.306,101.013 84.056,101.013 84.158,101.115 84.158,101.521 84.259,101.623 84.463,101.623 84.564,101.521 84.564,101.115 84.666,101.013 85.037,101.013 85.677,101.653 85.677,102.563 85.778,102.664 85.982,102.664 86.083,102.563 86.083,101.697 86.185,101.595 86.388,101.595 86.49,101.697 86.49,102.563 86.591,102.664 86.794,102.664 86.896,102.563 86.896,101.697 86.998,101.595 87.201,101.595 87.302,101.697 87.302,102.563 87.404,102.664 87.607,102.664 87.709,102.563 87.709,101.697 87.81,101.595 88.014,101.595 88.115,101.697 88.115,102.563 88.217,102.664 88.42,102.664 88.522,102.563 88.522,101.697 88.623,101.595 90.952,101.595 91.869,102.512 92.606,102.512 98.854,108.76 98.854,118.057 101.397,120.599 v1(101.826,120.599)
  Bottom Layer w0.127: v1(75.029,112.443) 74.775,112.443 74.648,112.316 74.648,111.808 74.775,111.681 75.156,111.681 75.283,111.808 75.283,111.935 75.537,112.189 76.045,112.189 76.683,111.552 90.561,111.552 99.609,120.599 v1(101.826,120.599) ; v1(75.052,100.759) 75.479,100.333 R322.2@75.479,96.468
QSPI_BK2_IO3: CN6.36 R116.1 R169.1 R319.1 | length 97.5
  Top Layer w0.127: R116.1@82.771,120.701 83.795,120.701 v1(84.935,121.841) ; 90.244,99.469 90.244,99.428 ; R169.1@90.244,100.175 90.244,99.428 ; v1(91.92,99.743) 91.92,99.388 92.456,98.852 92.456,97.942 92.301,97.787 91.818,97.787 91.691,97.914 91.691,98.93 91.336,99.286 91.336,99.972 91.209,100.099 90.952,100.099 90.825,99.972 90.825,99.39 90.658,99.223 90.449,99.223 90.244,99.428 ; v1(102.842,128.191) 102.87,128.219 CN6.36@104.965,128.221
  L4_SIG w0.102: v1(91.92,99.743) 91.92,100.124 91.615,100.429 86.053,100.429 85.951,100.531 85.951,100.81 86.053,100.912 91.183,100.912 91.539,101.267 93.139,101.267 93.368,101.496 93.368,102.332 99.515,108.478 99.515,117.777 101.547,119.809 102.461,119.809 102.69,120.038 102.69,121.356 102.537,121.511 102.537,122.171 102.842,122.476 103.096,122.476 103.985,123.365 103.985,127.048 v1(102.842,128.191)
  Bottom Layer w0.127: v1(84.935,121.841) 89.253,121.841 89.38,121.968 89.38,124.127 89.507,124.254 89.761,124.254 89.888,124.127 89.888,122.476 90.015,122.349 90.269,122.349 90.396,122.476 90.396,124.127 90.523,124.254 92.652,124.254 94.176,125.778 95.796,125.778 97.32,127.302 101.318,127.302 101.572,127.556 105.001,127.556 105.128,127.683 105.128,128.064 105.001,128.191 v1(102.842,128.191) ; R319.1@90.247,105.485 90.35,105.588 91.144,105.588 91.35,105.381 92.238,104.963 92.837,104.364 92.837,101.445 92.624,100.843 v1(91.92,99.743)
QSPI_BK2_NCS: CN5.34 R90.2 R166.2 SB120.1 U54.7 | length 106
  Top Layer w0.127: CN5.34@36.385,129.491 38.382,129.489 v1(38.504,129.588) ; v1(49.629,129.461) 49.629,129.334 50.264,128.702 50.602,128.364 R90.2@51.569,128.366 ; v1(75.791,110.284) 79.601,106.474 92.174,106.474 92.682,105.966 92.682,102.232 v1(92.159,101.709) 91.691,102.177 R166.2@91.26,102.178
  L4_SIG w0.102: v1(38.504,129.588) 43.66,129.588 49.604,123.645 50.571,123.645 51.943,125.016 51.943,127.257 55.306,130.621 57.822,130.621 64.315,124.127 69.624,124.127 71.018,122.733 71.018,118.25 73.124,116.144 73.124,114.224 74.521,112.827 74.521,111.554 v1(75.791,110.284)
  Bottom Layer w0.127: v1(38.504,129.588) 38.504,130.244 38.992,130.731 44.722,130.731 45.789,129.667 49.423,129.667 v1(49.629,129.461) ; U54.7@87.454,97.839 89.38,97.838 89.761,98.219 89.761,99.032 90.635,99.906 SB120.1@90.635,101.349 91.93,101.349 92.159,101.577 v1(92.159,101.709)
QSPI_CLK: CN6.42 R129.1 SB36.2 SB119.2 U12.16 | length 95.6
  Top Layer w0.127: v1(74.369,97.864) 74.369,97.61 74.648,97.33 75.776,97.33 75.903,97.203 75.903,96.571 SB36.2@75.901,96.572 75.9,95.189 76.172,94.917 79.22,94.917 79.474,95.171 79.474,96.187 79.093,96.568 U12.16@78.354,96.569 ; R129.1@82.807,114.623 83.898,114.623 v1(84.135,114.386) ; v1(103.033,124.409) CN6.42@104.965,124.411
  L4_SIG w0.102: v1(74.369,97.864) 74.775,98.6 74.775,98.981 74.62,99.87 74.62,100.985 75.029,101.394 82.42,101.394 85.595,103.071 90.294,103.071 91.996,104.772 92.885,104.772 97.838,109.728 97.838,118.491 98.662,119.315 98.665,119.315 100.711,121.361 100.711,122.885 102.235,124.409 v1(103.033,124.409)
  Bottom Layer w0.127: v1(74.369,97.864) 74.775,98.473 74.775,98.877 74.521,100.353 74.521,104.143 SB119.2@74.897,105.408 ; v1(84.135,114.386) 84.657,114.91 84.718,114.971 85.247,114.971 85.598,114.62 85.598,114.221 85.915,113.904 89.983,113.904 92.558,116.478 92.558,116.745 92.31,116.992 92.31,117.297 92.463,117.45 92.659,117.45 92.964,117.145 93.193,117.145 93.396,117.348 93.396,117.602 92.956,118.041 92.956,119.869 93.569,120.482 94.267,120.482 97.468,123.683 101.509,123.683 101.699,123.873 102.497,123.873 v1(103.033,124.409)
